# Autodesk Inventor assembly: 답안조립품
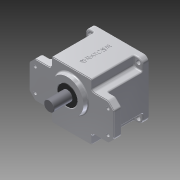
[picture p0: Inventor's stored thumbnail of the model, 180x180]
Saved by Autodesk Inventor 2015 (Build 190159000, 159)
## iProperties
Created: 2016-02
Part Number: 답안조립품
Document SubType Name: Assembly
Designer: Administrator
Author: Administrator
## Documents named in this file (10)
- C:\Users\Administrator\Desktop\460209V1013\답안조립품.iam
- C:\Users\Administrator\Desktop\460209V1013\본체.ipt
- C:\Users\Administrator\Desktop\460209V1013\커버.ipt
- C:\Users\Administrator\Desktop\460209V1013\볼트 M4 x 10.ipt
- C:\Users\Administrator\Desktop\460209V1013\오일실 17 32 8.ipt
- C:\Users\Administrator\Desktop\460209V1013\오일실 8 22 7.ipt
- C:\Users\Administrator\Desktop\460209V1013\베어링 608.ipt
- C:\Users\Administrator\Desktop\460209V1013\메인축.ipt
- C:\Users\Administrator\Desktop\460209V1013\서브축.ipt
- C:\Users\Administrator\Desktop\460209V1013\베어링 6003.ipt
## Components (2 placed, 1 different names)
1. ISO 4762 M4 x 10:1 — Insert:2
2. ISO 4762 M4 x 10:2 — Insert:1
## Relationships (2: Insert 2)
- Insert:1: ISO 4762 M4 x 10:2
- Insert:2: ISO 4762 M4 x 10:1
